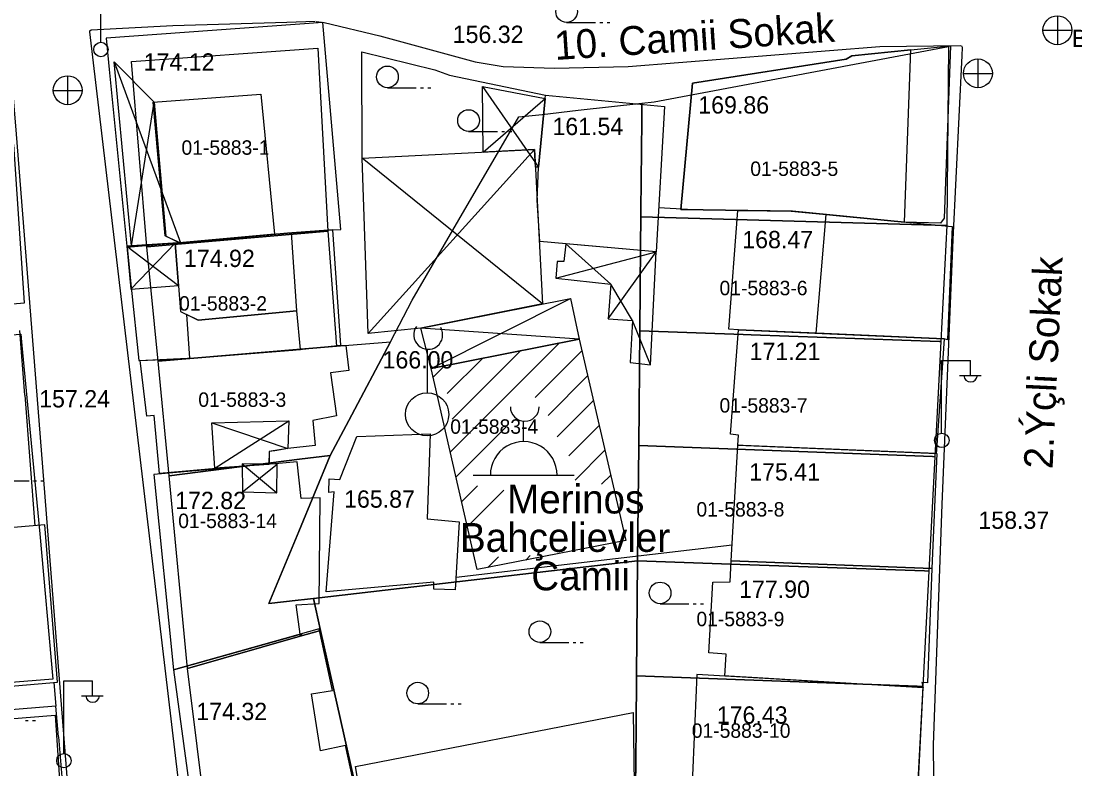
# Model space of a CAD drawing. Extents: x 419101 to 420177, y 4451541 to 4452254.
# Drawn here: x 419678.8 to 419751.9, y 4451680.3 to 4451732.1 of the extents above; entities that cross this region are included whole.
import ezdxf

# ---------------------------------------------------------------- set-up
doc = ezdxf.new("R2010")
doc.units = 0
doc.layers.add('2_KADASTRO', color=7, linetype='Continuous')
doc.layers.add('3_HALİHAZIR', color=7, linetype='Continuous')

msp = doc.modelspace()

# ---------------------------------------------------------------- linework, layer by layer
at = {"layer": '2_KADASTRO'}
for points in [[(419686.493, 4451729.31), (419699.405, 4451730.233), (419700.091, 4451717.553), (419687.562, 4451716.463)], [(419721.794, 4451718.543), (419721.798, 4451718.991), (419721.856, 4451725.224), (419721.867, 4451726.414), (419722.721, 4451726.52), (419725.789, 4451727.094), (419743.117, 4451730.335), (419743.01, 4451717.942), (419729.169, 4451718.334)], [(419696.023, 4451691.758), (419698.091, 4451696.755), (419700.268, 4451702.018), (419701.547, 4451704.433), (419704.437, 4451709.891), (419705.958, 4451712.764), (419709.177, 4451718.343), (419713.341, 4451725.465), (419714.954, 4451725.644), (419717.459, 4451725.923), (419721.867, 4451726.414), (419721.856, 4451725.224), (419721.798, 4451718.991), (419721.794, 4451718.543), (419721.776, 4451716.533), (419721.721, 4451710.636), (419721.648, 4451702.709), (419721.574, 4451694.713), (419699.1, 4451692.114), (419698.479, 4451692.042), (419698.048, 4451691.992)], [(419721.721, 4451710.636), (419721.776, 4451716.533), (419721.794, 4451718.543), (419729.169, 4451718.334), (419743.01, 4451717.942), (419742.588, 4451709.915), (419742.508, 4451709.917), (419729.437, 4451710.369), (419728.899, 4451710.388)], [(419687.562, 4451716.463), (419700.091, 4451717.553), (419700.699, 4451709.576), (419688.333, 4451708.534)], [(419640.217, 4451693.387), (419660.205, 4451695.026), (419659.044, 4451708.982), (419678.828, 4451710.413), (419678.901, 4451709.623), (419680.141, 4451696.581), (419681.032, 4451686.518), (419661.104, 4451684.921), (419641.21, 4451683.297)], [(419721.648, 4451702.709), (419721.721, 4451710.636), (419728.899, 4451710.388), (419729.437, 4451710.369), (419742.508, 4451709.917), (419742.588, 4451709.915), (419742.169, 4451701.927), (419742.009, 4451701.933), (419729.06, 4451702.426)], [(419688.333, 4451708.534), (419700.699, 4451709.576), (419704.437, 4451709.891), (419701.547, 4451704.433), (419700.268, 4451702.018), (419698.135, 4451701.748), (419689.105, 4451700.604)], [(419721.574, 4451694.713), (419721.648, 4451702.709), (419729.06, 4451702.426), (419742.009, 4451701.933), (419742.169, 4451701.927), (419741.753, 4451694.003), (419741.455, 4451694.013), (419728.682, 4451694.451)], [(419689.105, 4451700.604), (419698.135, 4451701.748), (419700.268, 4451702.018), (419698.091, 4451696.755), (419696.023, 4451691.758), (419698.048, 4451691.992), (419698.479, 4451692.042), (419699.1, 4451692.114), (419699.597, 4451689.894), (419698.025, 4451689.443), (419690.378, 4451687.251)], [(419699.1, 4451692.114), (419721.574, 4451694.713), (419721.501, 4451686.737), (419721.468, 4451683.159), (419721.429, 4451678.913), (419721.411, 4451676.975), (419721.311, 4451666.137), (419705.66, 4451662.842), (419701.901, 4451679.616), (419699.597, 4451689.894)], [(419721.501, 4451686.737), (419721.574, 4451694.713), (419728.682, 4451694.451), (419741.455, 4451694.013), (419741.753, 4451694.003), (419741.333, 4451686.011), (419740.96, 4451686.025), (419727.738, 4451686.508)], [(419690.378, 4451687.251), (419698.025, 4451689.443), (419699.597, 4451689.894), (419701.901, 4451679.616), (419705.66, 4451662.842), (419693.748, 4451660.167)], [(419721.429, 4451678.913), (419721.468, 4451683.159), (419721.501, 4451686.737), (419727.738, 4451686.508), (419740.96, 4451686.025), (419741.333, 4451686.011), (419740.919, 4451678.122), (419740.659, 4451678.133), (419729.18, 4451678.602), (419725.72, 4451678.743)], [(419631.759, 4451680.024), (419681.199, 4451684.024), (419681.57, 4451678.497), (419669.409, 4451675.717), (419660.668, 4451673.719), (419657.184, 4451672.922), (419656.658, 4451677.991), (419631.896, 4451676.656)]]:
    msp.add_lwpolyline(points, close=True, dxfattribs=at)
at = {"layer": '3_HALİHAZIR'}
for p, q in [((419684.362, 4451730.661), (419684.362, 4451735.661)), ((419750.668, 4451732.471), (419750.668, 4451730.471)), ((419716.653, 4451732.013), (419718.653, 4451732.013)), ((419718.953, 4451732.013), (419719.153, 4451732.013)), ((419719.453, 4451732.013), (419719.653, 4451732.013)), ((419749.668, 4451731.471), (419751.668, 4451731.471)), ((419745.175, 4451727.475), (419745.175, 4451729.475)), ((419685.292, 4451729.274), (419689.879, 4451716.752)), ((419682.082, 4451726.305), (419682.082, 4451728.305)), ((419744.155, 4451728.465), (419746.155, 4451728.465)), ((419681.062, 4451727.295), (419683.062, 4451727.295)), ((419704.233, 4451727.49), (419706.233, 4451727.49)), ((419706.533, 4451727.49), (419706.733, 4451727.49)), ((419707.033, 4451727.49), (419707.233, 4451727.49)), ((419710.831, 4451727.583), (419714.706, 4451721.989)), ((419686.505, 4451716.535), (419688.072, 4451726.498)), ((419710.867, 4451723.035), (419715.172, 4451726.731)), ((419709.853, 4451724.467), (419711.853, 4451724.467)), ((419712.153, 4451724.467), (419712.353, 4451724.467)), ((419712.653, 4451724.467), (419712.853, 4451724.467)), ((419702.897, 4451710.459), (419714.421, 4451723.214)), ((419714.992, 4451712.506), (419702.473, 4451722.613)), ((419686.18, 4451716.515), (419689.751, 4451713.781)), ((419689.519, 4451716.72), (419686.451, 4451713.533)), ((419716.597, 4451716.682), (419719.722, 4451713.869)), ((419715.904, 4451714.294), (419722.863, 4451716.124)), ((419719.535, 4451711.482), (419722.863, 4451716.124)), ((419707.274, 4451708.037), (419716.92, 4451712.89)), ((419717.513, 4451710.074), (419706.552, 4451710.825)), ((419708.594, 4451702.266), (419716.131, 4451709.799)), ((419706.983, 4451709.367), (419706.983, 4451706.361)), ((419708.731, 4451704.523), (419713.484, 4451709.274)), ((419714.468, 4451706.017), (419717.705, 4451709.252)), ((419707.41, 4451707.444), (419708.19, 4451708.223)), ((419708.384, 4451706.297), (419710.837, 4451708.748)), ((419742.647, 4451703.583), (419742.647, 4451708.583)), ((419742.647, 4451708.583), (419744.647, 4451708.583)), ((419744.647, 4451707.583), (419744.647, 4451708.583)), ((419715.363, 4451704.791), (419718.106, 4451707.532)), ((419743.887, 4451707.543), (419745.387, 4451707.543)), ((419715.992, 4451703.299), (419718.507, 4451705.813)), ((419692.064, 4451704.263), (419697.327, 4451702.487)), ((419692.263, 4451701.127), (419697.39, 4451704.4)), ((419708.989, 4451700.539), (419712.478, 4451704.027)), ((419713.668, 4451702.973), (419713.668, 4451704.388)), ((419716.804, 4451701.99), (419718.908, 4451704.094)), ((419717.234, 4451700.299), (419719.31, 4451702.374)), ((419694.169, 4451701.438), (419696.574, 4451699.424)), ((419694.199, 4451699.5), (419696.594, 4451701.403)), ((419677.404, 4451700.248), (419679.404, 4451700.248)), ((419679.704, 4451700.248), (419679.904, 4451700.248)), ((419680.204, 4451700.248), (419680.404, 4451700.248)), ((419710.168, 4451700.638), (419717.168, 4451700.638)), ((419719.074, 4451700.018), (419719.711, 4451700.655)), ((419709.383, 4451698.813), (419710.47, 4451699.899)), ((419709.778, 4451697.087), (419712.293, 4451699.602)), ((419711.181, 4451694.249), (419711.926, 4451694.993)), ((419713.818, 4451694.765), (419714.131, 4451695.077)), ((419723.133, 4451691.737), (419725.133, 4451691.737)), ((419725.433, 4451691.737), (419725.633, 4451691.737)), ((419725.933, 4451691.737), (419726.133, 4451691.737)), ((419714.8, 4451689.056), (419716.8, 4451689.056)), ((419717.1, 4451689.056), (419717.3, 4451689.056)), ((419717.6, 4451689.056), (419717.8, 4451689.056)), ((419681.798, 4451681.392), (419681.798, 4451686.392)), ((419681.798, 4451686.392), (419683.798, 4451686.392)), ((419683.798, 4451685.392), (419683.798, 4451686.392)), ((419683.038, 4451685.352), (419684.538, 4451685.352)), ((419706.333, 4451684.802), (419708.333, 4451684.802)), ((419708.633, 4451684.802), (419708.833, 4451684.802)), ((419709.133, 4451684.802), (419709.333, 4451684.802)), ((419679.14, 4451683.649), (419679.34, 4451683.649)), ((419679.64, 4451683.649), (419679.84, 4451683.649))]:
    msp.add_line(p, q, dxfattribs=at)
for points in [[(419675.282, 4451751.118), (419676.056, 4451748.782), (419676.481, 4451747.072), (419677.045, 4451741.588), (419678.504, 4451724.263), (419680.007, 4451705.319), (419682.289, 4451676.241), (419684.885, 4451657.607), (419684.872, 4451657.072), (419684.76, 4451656.663), (419684.634, 4451656.556), (419684.325, 4451656.372), (419683.717, 4451656.008)], [(419704.927, 4451660.359), (419694.778, 4451658.462), (419693.279, 4451658.204), (419693.059, 4451658.213), (419692.824, 4451658.303), (419692.4, 4451658.697), (419692.214, 4451659.076), (419692.138, 4451659.379), (419683.595, 4451731.355), (419683.617, 4451731.434), (419683.705, 4451731.496), (419689.351, 4451731.793)], [(419689.351, 4451731.793), (419697.259, 4451732.027), (419699.22, 4451732.091)], [(419699.285, 4451732.074), (419699.837, 4451732.008), (419703.717, 4451731.073), (419710.313, 4451729.273), (419712.254, 4451728.948), (419715.817, 4451728.854), (419720.916, 4451728.957), (419738.359, 4451730.346), (419743.922, 4451730.418), (419744.015, 4451730.386), (419744.063, 4451730.309), (419744.061, 4451730.271), (419744.043, 4451729.713)], [(419702.473, 4451722.613), (419702.449, 4451729.983), (419707.528, 4451728.723)], [(419744.043, 4451729.713), (419743.411, 4451716.983), (419742.655, 4451698.624), (419742.051, 4451681.971), (419742.175, 4451670.696), (419742.12, 4451670.379), (419742.009, 4451670.098), (419741.86, 4451669.79), (419741.65, 4451669.489), (419741.394, 4451669.2), (419741.194, 4451669.026), (419740.817, 4451668.77), (419740.466, 4451668.579), (419740.144, 4451668.405), (419739.786, 4451668.242), (419738.631, 4451667.903), (419729.666, 4451665.936)], [(419707.528, 4451728.723), (419708.527, 4451728.36)], [(419708.527, 4451728.36), (419715.196, 4451726.97)], [(419673.314, 4451712.108), (419679.071, 4451712.584), (419678.329, 4451723.562), (419674.764, 4451723.316), (419674.624, 4451724.553), (419673.445, 4451724.441)], [(419725.026, 4451719.047), (419723.034, 4451719.161)], [(419722.461, 4451708.301), (419721.216, 4451711.361), (419719.722, 4451713.869)], [(419679.094, 4451706.19), (419678.743, 4451710.658)], [(419679.094, 4451706.19), (419679.803, 4451697.148)], [(419673.032, 4451685.589), (419681.368, 4451686.318), (419680.492, 4451697.206), (419676.664, 4451696.881), (419676.601, 4451697.762), (419673.499, 4451697.525), (419673.563, 4451696.665), (419673.149, 4451696.646)], [(419728.128, 4451695.788), (419708.988, 4451693.552)], [(419681.104, 4451686.295), (419681.247, 4451684.646)], [(419681.247, 4451684.646), (419673.015, 4451683.972)], [(419681.433, 4451682.509), (419681.247, 4451684.646)], [(419681.433, 4451682.509), (419681.769, 4451678.651)]]:
    msp.add_lwpolyline(points, dxfattribs=at)
for points in [[(419700.456, 4451717.637), (419700.993, 4451717.659), (419699.746, 4451732.01), (419684.731, 4451730.91), (419684.955, 4451728.752), (419686.18, 4451716.515), (419689.788, 4451716.744), (419697.295, 4451717.414), (419700.456, 4451717.637)], [(419740.512, 4451730.106), (419743.251, 4451730.396), (419742.821, 4451718.449), (419742.557, 4451718.113), (419740.068, 4451718.164), (419732.298, 4451718.925), (419724.561, 4451719.055), (419725.372, 4451727.812), (419736.028, 4451729.46), (419736.41, 4451729.706)], [(419725.372, 4451727.812), (419724.561, 4451719.055), (419732.298, 4451718.925), (419740.068, 4451718.164), (419740.512, 4451730.106), (419736.41, 4451729.706), (419736.028, 4451729.46)], [(419686.505, 4451716.535), (419685.292, 4451729.274), (419688.072, 4451726.498), (419688.876, 4451717.215), (419689.879, 4451716.752), (419689.359, 4451716.71)], [(419710.867, 4451723.035), (419710.831, 4451727.583), (419715.172, 4451726.731), (419714.706, 4451721.989), (419714.487, 4451721.981), (419714.421, 4451723.214)], [(419689.788, 4451716.744), (419688.828, 4451717.239), (419687.993, 4451726.492), (419695.464, 4451727.053), (419696.416, 4451717.336)], [(419714.806, 4451716.841), (419714.608, 4451719.709), (419714.706, 4451721.989), (419715.172, 4451726.731), (419715.196, 4451726.97), (419723.429, 4451726.192), (419722.863, 4451716.124)], [(419714.992, 4451712.506), (419706.552, 4451710.825), (419702.897, 4451710.459), (419702.473, 4451722.613), (419714.421, 4451723.214)], [(419728.866, 4451718.983), (419732.218, 4451718.927), (419734.639, 4451718.696), (419743.379, 4451717.869), (419743.054, 4451710.032), (419742.812, 4451710.099), (419733.97, 4451710.48), (419728.577, 4451710.713), (419727.893, 4451710.771), (419728.53, 4451718.989)], [(419733.948, 4451710.481), (419734.639, 4451718.696), (419736.022, 4451718.561), (419743.379, 4451717.869), (419743.054, 4451710.032), (419742.812, 4451710.099), (419733.97, 4451710.48)], [(419686.47, 4451713.671), (419686.991, 4451708.596), (419691.336, 4451708.809), (419697.903, 4451709.335), (419700.994, 4451709.655), (419700.456, 4451717.637), (419697.295, 4451717.414), (419689.554, 4451716.726), (419686.188, 4451716.428)], [(419689.519, 4451716.72), (419689.891, 4451711.994), (419691.105, 4451711.376), (419697.942, 4451712.029), (419697.58, 4451717.44)], [(419689.519, 4451716.72), (419686.18, 4451716.515), (419686.451, 4451713.533), (419689.751, 4451713.781)], [(419716.597, 4451716.682), (419716.465, 4451715.457), (419716, 4451715.459), (419715.904, 4451714.294), (419719.722, 4451713.869), (419719.535, 4451711.482), (419721.216, 4451711.361), (419721.063, 4451708.442), (419722.461, 4451708.301), (419722.863, 4451716.124)], [(419717.513, 4451710.074), (419707.274, 4451708.037), (419706.552, 4451710.825), (419716.92, 4451712.89)], [(419690.317, 4451711.777), (419690.511, 4451708.743), (419698.198, 4451709.359), (419697.942, 4451712.029), (419691.105, 4451711.376)], [(419728.555, 4451702.726), (419728.518, 4451702.728), (419728.561, 4451703.407), (419728, 4451703.493), (419728.577, 4451710.713), (419742.812, 4451710.099), (419742.286, 4451702.407), (419742.274, 4451702.139), (419728.879, 4451702.712)], [(419688.43, 4451700.771), (419688.063, 4451704.774), (419687.553, 4451704.741), (419687.084, 4451708.6), (419690.708, 4451708.758), (419697.679, 4451709.317), (419700.994, 4451709.655), (419701.353, 4451709.63), (419701.547, 4451707.891), (419700.292, 4451707.743), (419700.71, 4451704.754), (419699.068, 4451704.429), (419699.235, 4451702.709), (419697.327, 4451702.487), (419696.429, 4451702.341), (419696.032, 4451702.276), (419696.027, 4451701.441)], [(419710.459, 4451694.109), (419707.274, 4451708.037), (419717.513, 4451710.074), (419720.768, 4451696.125)], [(419692.263, 4451701.127), (419692.064, 4451704.263), (419697.39, 4451704.4), (419697.327, 4451702.487), (419696.032, 4451702.276), (419696.016, 4451701.394)], [(419699.997, 4451692.574), (419700.532, 4451699.483), (419700.164, 4451699.452), (419700.195, 4451700.395), (419700.93, 4451700.344), (419702.109, 4451703.322), (419707.193, 4451703.504), (419706.989, 4451697.614), (419709.211, 4451697.423), (419708.939, 4451692.696), (419707.453, 4451692.752), (419707.45, 4451693.245)], [(419728.067, 4451694.717), (419728.518, 4451702.728), (419742.307, 4451702.137), (419741.958, 4451694.174)], [(419698.209, 4451689.479), (419697.914, 4451691.675), (419699.491, 4451691.763), (419699.581, 4451699.069), (419698.247, 4451699.035), (419697.985, 4451701.573), (419696.699, 4451701.465), (419693.954, 4451701.242), (419693.034, 4451701.131), (419688.043, 4451700.685), (419689.411, 4451687.168), (419698.296, 4451689.661)], [(419694.169, 4451701.438), (419694.199, 4451699.5), (419696.574, 4451699.424), (419696.594, 4451701.403)], [(419727.609, 4451686.73), (419727.702, 4451688.254), (419726.521, 4451688.338), (419726.797, 4451693.244), (419727.981, 4451693.253), (419728.067, 4451694.717), (419741.958, 4451694.174), (419741.662, 4451686.25), (419741.273, 4451686.281), (419741.358, 4451685.917), (419729.483, 4451686.619), (419727.889, 4451686.713)], [(419703.246, 4451673.163), (419701.325, 4451681.917), (419699.589, 4451681.558), (419698.961, 4451685.49), (419700.434, 4451685.74), (419699.505, 4451690.001), (419689.411, 4451687.168), (419693.117, 4451659.783), (419699.76, 4451661.296), (419705.604, 4451662.865), (419704.843, 4451666.075), (419704.032, 4451671.075), (419703.735, 4451671.046)], [(419725.679, 4451686.844), (419725.334, 4451678.757), (419740.964, 4451678.125), (419741.358, 4451685.917)], [(419721.151, 4451665.996), (419705.604, 4451662.865), (419704.843, 4451666.075), (419704.032, 4451671.075), (419703.735, 4451671.046), (419703.43, 4451672.497), (419703.246, 4451673.163), (419702.013, 4451680.471), (419721.268, 4451684.216), (419721.348, 4451677.61)]]:
    msp.add_lwpolyline(points, close=True, dxfattribs=at)
for centre, radius in [((419716.653, 4451732.763), 0.75), ((419750.668, 4451731.471), 1), ((419684.372, 4451730.137), 0.5), ((419745.16, 4451728.484), 1), ((419704.233, 4451728.24), 0.75), ((419682.067, 4451727.313), 1), ((419709.853, 4451725.217), 0.75), ((419706.983, 4451704.861), 1.5), ((419742.658, 4451703.058), 0.5), ((419723.133, 4451692.487), 0.75), ((419714.8, 4451689.806), 0.75), ((419706.333, 4451685.552), 0.75), ((419681.808, 4451680.868), 0.5)]:
    msp.add_circle(centre, radius, dxfattribs=at)
for centre, radius, start, end in [((419707.061, 4451710.364), 1, 143.60214, 30.48893), ((419744.648, 4451707.587), 0.474, 184.83843, 355.14641), ((419713.752, 4451705.384), 1, 180, 0), ((419713.679, 4451700.66), 2.313, 359.45576, 180.54424), ((419683.798, 4451685.396), 0.474, 184.83843, 355.14641)]:
    msp.add_arc(centre, radius, start, end, dxfattribs=at)

# ---------------------------------------------------------------- texts
at = {"layer": '2_KADASTRO'}
for s, p in [('01-5883-1', (419689.958, 4451722.844)), ('01-5883-5', (419729.383, 4451721.377)), ('01-5883-6', (419727.251, 4451713.112)), ('01-5883-2', (419689.789, 4451712.046)), ('01-5883-3', (419691.124, 4451705.38)), ('01-5883-7', (419727.25, 4451704.98)), ('01-5883-4', (419708.586, 4451703.514)), ('01-5883-8', (419725.65, 4451697.781)), ('01-5883-14', (419689.733, 4451696.982)), ('01-5883-9', (419725.65, 4451690.183)), ('01-5883-10', (419725.327, 4451682.451))]:
    msp.add_text(s, height=1, dxfattribs=at).set_placement(p)
at = {"layer": '3_HALİHAZIR'}
for s, height, rotation, p in [('10. Camii Sokak', 2, 3.73759, (419715.862, 4451729.406)), ('156.32 ', 1.2, 359.99714, (419708.759, 4451730.589)), ('174.12 ', 1.2, 359.99793, (419687.337, 4451728.67)), ('161.54 ', 1.2, 359.99793, (419715.669, 4451724.207)), ('174.92 ', 1.2, 359.99793, (419690.13, 4451715.067)), ('2.Ýçli Sokak', 2, 87.27876, (419750.333, 4451701.045)), ('166.00 ', 1.2, 359.99793, (419703.895, 4451708.037)), ('172.82 ', 1.2, 359.99793, (419689.523, 4451698.296)), ('165.87 ', 1.2, 359.99793, (419701.228, 4451698.393)), ('158.37 ', 1.2, 359.99714, (419745.194, 4451696.929)), ('177.90 ', 1.2, 359.99793, (419728.606, 4451692.145)), ('174.32 ', 1.2, 359.99793, (419690.985, 4451683.677))]:
    msp.add_text(s, height=height, rotation=rotation, dxfattribs=at).set_placement(p)
for s, height, p in [('B', 1.2, (419751.668, 4451730.309)), ('169.86', 1.2, (419725.779, 4451725.698)), ('168.47', 1.2, (419728.828, 4451716.367)), ('171.21', 1.2, (419729.336, 4451708.622)), ('157.24 ', 1.2, (419680.094, 4451705.339)), ('175.41', 1.2, (419729.307, 4451700.277)), ('Merinos', 2, (419712.528, 4451697.993)), ('Bahçelievler', 2, (419709.261, 4451695.331)), ('Camii', 2, (419714.204, 4451692.669)), ('176.43', 1.2, (419727.06, 4451683.431))]:
    msp.add_text(s, height=height, dxfattribs=at).set_placement(p)

doc.saveas('drawing.dxf')
